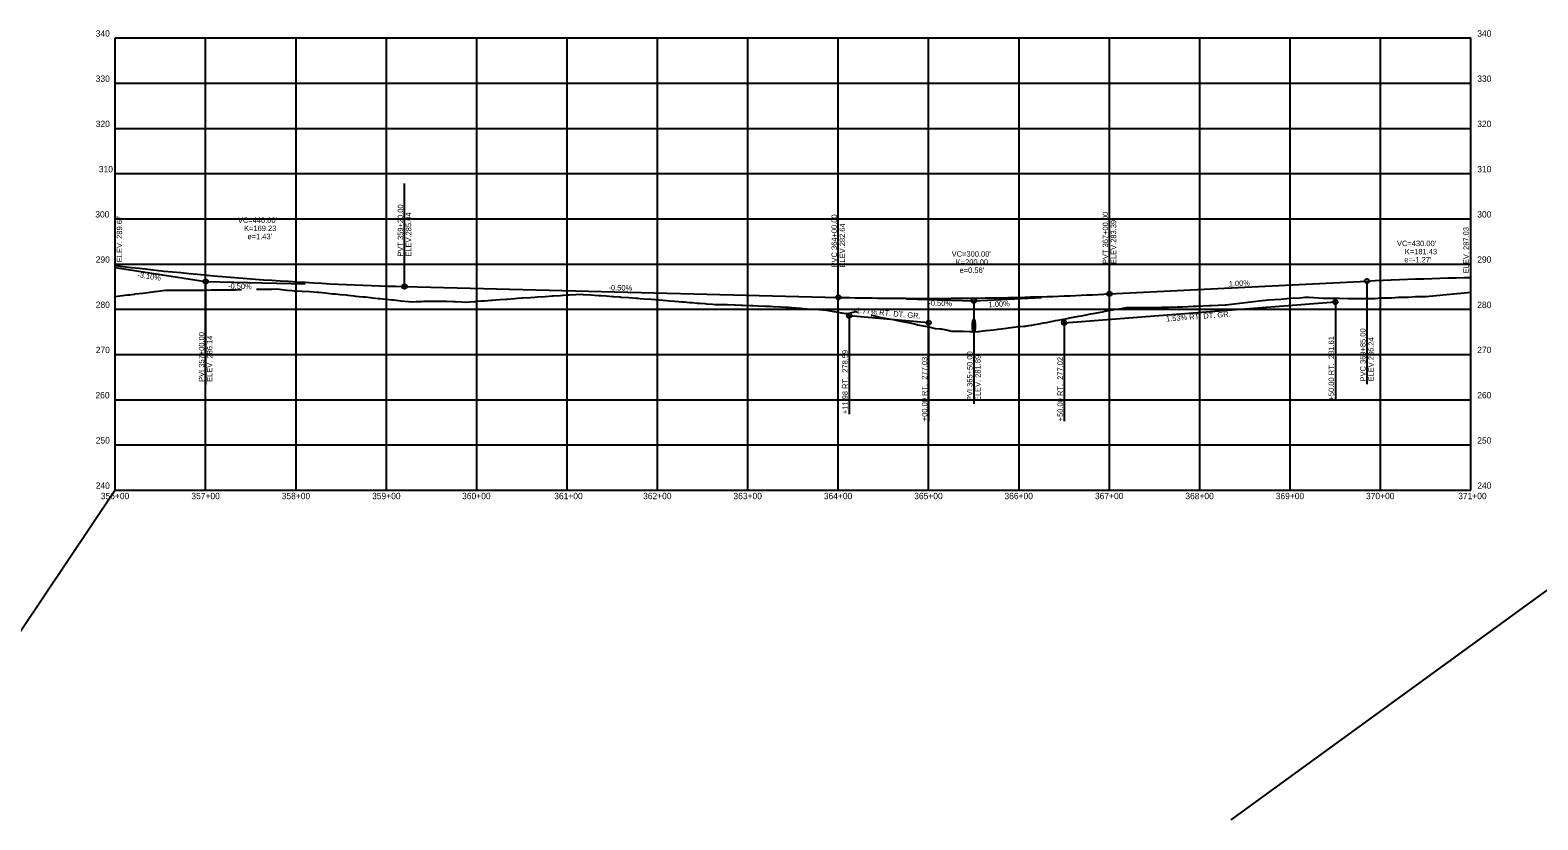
# Model space of a CAD drawing. Extents: x 881054 to 892094, y 1562235 to 1563136.
# Drawn here: x 886308 to 887976, y 1562253 to 1563127 of the extents above; entities that cross this region are included whole.
import ezdxf

# ---------------------------------------------------------------- set-up
doc = ezdxf.new("R2010")
doc.units = 0
for name, color, linetype in [('Default', 7, 'Continuous'), ('R_Axis', 7, 'Continuous'), ('R_Axis Annot', 7, 'Continuous'), ('R_Concrete', 7, 'Continuous'), ('R_Exist Surface', 7, 'Continuous'), ('R_Grid', 7, 'Continuous'), ('R_No Plot', 7, 'Continuous'), ('R_Point Sym', 7, 'Continuous'), ('R_Vert Alg', 7, 'Continuous'), ('R_Vert Alg Annot', 7, 'Continuous')]:
    doc.layers.add(name, color=color, linetype=linetype)

msp = doc.modelspace()

# ---------------------------------------------------------------- linework, layer by layer
at = {"layer": 'Default'}
for p, q in [((887452.2, 1562803), (887752.2, 1562826)), ((887214.2, 1562810.9), (887302.2, 1562803.1))]:
    msp.add_line(p, q, dxfattribs=at)
at = {"layer": 'R_Axis'}
for p, q in [((886402.2, 1562617.9), (886402.2, 1563117.9)), ((887902.2, 1562617.9), (887902.2, 1563117.9)), ((886402.2, 1562617.9), (887902.2, 1562617.9))]:
    msp.add_line(p, q, dxfattribs=at)
at = {"layer": 'R_Concrete'}
msp.add_ellipse((887352.2, 1562799.6), major_axis=(0, 7.5), ratio=0.2, dxfattribs=at)
at = {"layer": 'R_Exist Surface'}
for points in [[(886402.2, 1562832.2), (886407.4, 1562832.7), (886415.8, 1562833.7), (886418.4, 1562834), (886420.7, 1562834.3), (886423.7, 1562834.7), (886424.2, 1562834.8), (886432.6, 1562835.8), (886441, 1562836.8), (886441, 1562836.8), (886445.9, 1562837.5), (886449.4, 1562837.9), (886457.8, 1562838.9), (886458.7, 1562839.1), (886466.2, 1562839.1), (886467.8, 1562839.1), (886474.6, 1562839.1), (886479.3, 1562839.2), (886483, 1562839.1), (886484.9, 1562839.1), (886491.4, 1562839.2), (886498.8, 1562839.2), (886499.8, 1562839.2), (886501.9, 1562839.2), (886508.2, 1562839.3), (886516.6, 1562839.3), (886518.3, 1562839.4), (886518.7, 1562839.4), (886521.4, 1562839.4), (886525, 1562839.4), (886533.4, 1562839.3), (886534.7, 1562839.3), (886541.8, 1562839.7)], [(886558.3, 1562840), (886558.6, 1562840), (886560.1, 1562840), (886567, 1562840.2), (886572, 1562840.2), (886575.5, 1562840.3), (886580.6, 1562840.4), (886583.9, 1562840), (886589.2, 1562839.4), (886592.3, 1562839.1), (886597.5, 1562838.5), (886600.7, 1562838.3), (886609.1, 1562837.8), (886617.5, 1562837.4), (886625.9, 1562836.9), (886627.6, 1562836.8), (886634.3, 1562836.1), (886636.9, 1562835.8), (886642.7, 1562835.1), (886645.9, 1562834.8), (886651.1, 1562834.3), (886657.7, 1562833.7), (886659.5, 1562833.4), (886666.2, 1562832.7), (886667.9, 1562832.5), (886676.3, 1562831.7), (886678.9, 1562831.5), (886684.7, 1562830.8), (886687, 1562830.6), (886693.1, 1562829.9), (886695.1, 1562829.7), (886701.5, 1562829.1), (886708.1, 1562828.4), (886709.9, 1562828.2), (886715.8, 1562827.6), (886718.3, 1562827.4), (886726.7, 1562826.5), (886729.6, 1562826.3), (886735.1, 1562826.4), (886740.8, 1562826.5), (886743.6, 1562826.7), (886745.9, 1562826.9), (886752, 1562826.9), (886760.4, 1562826.9), (886760.5, 1562826.9), (886761.4, 1562827), (886764.5, 1562827), (886768.8, 1562826.7), (886775.9, 1562826.4), (886777.2, 1562826.4), (886778.2, 1562826.4), (886785.6, 1562826.1), (886789.9, 1562825.9), (886794, 1562826.2), (886800.9, 1562826.6), (886802.4, 1562826.8), (886806.6, 1562827.1), (886810.8, 1562827.4), (886818, 1562827.9), (886819.2, 1562828), (886823.3, 1562828.3), (886827.6, 1562828.6), (886835, 1562829.1), (886836, 1562829.2), (886844.4, 1562829.8), (886847.2, 1562830), (886852, 1562830.4), (886852.8, 1562830.5), (886861.2, 1562831), (886866.3, 1562831.4), (886869.4, 1562831.6), (886869.6, 1562831.6), (886878, 1562832.2), (886885.5, 1562832.7), (886886.4, 1562832.8), (886886.7, 1562832.8), (886894.8, 1562833.3), (886897.9, 1562833.5), (886903.2, 1562833.7), (886904.3, 1562833.8), (886911.7, 1562834.1), (886919.6, 1562834.5), (886920.1, 1562834.4), (886928.5, 1562833.8), (886936.9, 1562833.2), (886938.8, 1562833.1), (886940, 1562833), (886945.3, 1562832.6), (886952.3, 1562832.1), (886953.7, 1562832), (886959.8, 1562831.6), (886960.4, 1562831.5), (886961, 1562831.5), (886962.1, 1562831.4), (886970.5, 1562830.8), (886978.9, 1562830.2), (886980.4, 1562830.1), (886982.6, 1562829.9), (886987.3, 1562829.6), (886995.7, 1562829), (886999.9, 1562828.7), (887003.9, 1562828.3), (887004.1, 1562828.3), (887012.5, 1562827.6), (887015.4, 1562827.4), (887020.9, 1562826.9), (887021.2, 1562826.9), (887029.3, 1562826.2), (887031.7, 1562826), (887037.7, 1562825.5), (887040.6, 1562825.3), (887046.1, 1562824.8), (887048.6, 1562824.6), (887054.5, 1562824.1), (887056.5, 1562824), (887062.9, 1562823.5), (887066.1, 1562823.2), (887071.3, 1562823.2), (887076.2, 1562823.1), (887079.8, 1562823), (887087.2, 1562822.7), (887088.2, 1562822.7), (887094.8, 1562822.6), (887096.6, 1562822.5), (887105, 1562822.1), (887107.5, 1562822), (887113.4, 1562821.7), (887121.8, 1562821.3), (887123, 1562821.3), (887127, 1562821.2), (887130.2, 1562821.1), (887138.6, 1562820.6), (887144.2, 1562820.4), (887145.8, 1562820.3), (887147, 1562820.2), (887155.4, 1562819.4), (887155.5, 1562819.4), (887159.8, 1562819.1), (887160.4, 1562819), (887163.8, 1562818.8), (887172.2, 1562818.1), (887174.1, 1562817.9), (887176.5, 1562817.9), (887180.6, 1562817.6), (887189, 1562817), (887189, 1562817), (887197.4, 1562815.3), (887197.6, 1562815.3), (887205.8, 1562813.9), (887211.2, 1562813.1), (887214.2, 1562813.7), (887220, 1562814.9), (887221.9, 1562815.4), (887222.6, 1562815.1), (887223, 1562815)], [(887238.6, 1562811.5), (887239.4, 1562811.3), (887244.2, 1562810.1), (887247.9, 1562809.2), (887249.5, 1562808.8), (887256.3, 1562807.7), (887263, 1562806.5), (887264.7, 1562806.1), (887269.3, 1562805), (887273.1, 1562804.3), (887281.5, 1562802.8), (887281.8, 1562802.8), (887289.2, 1562800.9), (887289.9, 1562800.8), (887298.3, 1562799.3), (887300.7, 1562798.8), (887306.7, 1562797.3), (887309.3, 1562796.7), (887315.1, 1562796.3), (887316.2, 1562796.2), (887323.5, 1562794.7), (887327.6, 1562793.8), (887331.9, 1562793.8), (887336, 1562793.7), (887340.3, 1562793.6), (887347.7, 1562793.5), (887348.7, 1562793.3), (887350.6, 1562793), (887357.1, 1562793.3), (887357.3, 1562793.3), (887362.6, 1562794), (887365.1, 1562794.3), (887365.5, 1562794.3), (887373.9, 1562795.3), (887379, 1562796), (887382.3, 1562796.4), (887388.3, 1562797.1), (887390.7, 1562797.4), (887399.1, 1562798.3), (887403.4, 1562798.7), (887407.5, 1562799.2), (887409.4, 1562799.4), (887413.2, 1562799.9), (887416, 1562800.4), (887416.4, 1562800.4), (887419.6, 1562800.9), (887424.4, 1562801.9), (887429.4, 1562802.9), (887432.5, 1562803.4), (887432.8, 1562803.4), (887441.2, 1562805.1), (887442.4, 1562805.3), (887445.5, 1562805.8), (887449.6, 1562806.6), (887455.5, 1562807.8), (887458.5, 1562808.3), (887468.5, 1562810.2), (887471.4, 1562810.7), (887481.6, 1562812.7), (887484.4, 1562813.2), (887494.6, 1562815.2), (887497.3, 1562815.7), (887507.7, 1562817.7), (887511.2, 1562817.9), (887521.3, 1562819.9), (887525.3, 1562820), (887536.7, 1562819.7), (887542.7, 1562820), (887552.2, 1562819.8), (887560.1, 1562820.2), (887567.8, 1562820.1), (887577.5, 1562820.6), (887583.4, 1562820.6), (887595, 1562821.2), (887599.1, 1562821.2), (887612.5, 1562821.9), (887614.8, 1562822), (887630.1, 1562822.9), (887630.6, 1562822.9), (887631.1, 1562822.9), (887667.8, 1562827.2), (887678.4, 1562828.2), (887692, 1562829.2), (887701.8, 1562830.2), (887713.3, 1562830.7), (887718.8, 1562831.4), (887723, 1562831.4), (887739.1, 1562830.1), (887746.7, 1562830.1), (887756.7, 1562830), (887766.5, 1562829.9), (887774.1, 1562829.9), (887784.1, 1562829.9), (887795.8, 1562829.9), (887802.9, 1562830.5), (887814.5, 1562830.6), (887821.8, 1562831.3), (887833.2, 1562831.3), (887840.9, 1562832.1), (887852.1, 1562832.1), (887860.2, 1562832.9), (887871.6, 1562834), (887883, 1562835), (887891, 1562835.8), (887902.2, 1562836.8)]]:
    msp.add_lwpolyline(points, dxfattribs=at)
at = {"layer": 'R_Grid'}
for p, q in [((886402.2, 1563117.9), (887902.2, 1563117.9)), ((886402.2, 1563117.9), (887902.2, 1563117.9)), ((886502.2, 1562617.9), (886502.2, 1563117.9)), ((886602.2, 1562617.9), (886602.2, 1563117.9)), ((886702.2, 1562617.9), (886702.2, 1563117.9)), ((886802.2, 1562617.9), (886802.2, 1563117.9)), ((886902.2, 1562617.9), (886902.2, 1563117.9)), ((887002.2, 1562617.9), (887002.2, 1563117.9)), ((887102.2, 1562617.9), (887102.2, 1563117.9)), ((887202.2, 1562617.9), (887202.2, 1563117.9)), ((887302.2, 1562617.9), (887302.2, 1563117.9)), ((887402.2, 1562617.9), (887402.2, 1563117.9)), ((887502.2, 1562617.9), (887502.2, 1563117.9)), ((887602.2, 1562617.9), (887602.2, 1563117.9)), ((887702.2, 1562617.9), (887702.2, 1563117.9)), ((887802.2, 1562617.9), (887802.2, 1563117.9)), ((886402.2, 1563067.9), (887902.2, 1563067.9)), ((886402.2, 1563017.9), (887902.2, 1563017.9)), ((886402.2, 1562967.9), (887902.2, 1562967.9)), ((886402.2, 1562917.9), (887902.2, 1562917.9)), ((886402.2, 1562867.9), (887902.2, 1562867.9)), ((886402.2, 1562817.9), (887902.2, 1562817.9)), ((886402.2, 1562767.9), (887902.2, 1562767.9)), ((886402.2, 1562717.9), (887902.2, 1562717.9)), ((886402.2, 1562667.9), (887902.2, 1562667.9))]:
    msp.add_line(p, q, dxfattribs=at)
at = {"layer": 'R_No Plot'}
for p, q in [((886402.2, 1562617.9), (886232.6, 1562365.3)), ((888122.2, 1562606), (887636.7, 1562253.3))]:
    msp.add_line(p, q, dxfattribs=at)
at = {"layer": 'R_Point Sym'}
for points in [[(887752.2, 1562826), (887751.7, 1562826.5), (887752.2, 1562826), (887751.7, 1562825.5), (887752.2, 1562826), (887752.7, 1562825.5), (887752.2, 1562826), (887752.7, 1562826.5)], [(887214.2, 1562810.9), (887213.7, 1562811.4), (887214.2, 1562810.9), (887213.7, 1562810.4), (887214.2, 1562810.9), (887214.7, 1562810.4), (887214.2, 1562810.9), (887214.7, 1562811.4)], [(887302.2, 1562803.1), (887301.7, 1562803.6), (887302.2, 1562803.1), (887301.7, 1562802.6), (887302.2, 1562803.1), (887302.7, 1562802.6), (887302.2, 1562803.1), (887302.7, 1562803.6)], [(887452.2, 1562803), (887451.7, 1562803.5), (887452.2, 1562803), (887451.7, 1562802.5), (887452.2, 1562803), (887452.7, 1562802.5), (887452.2, 1562803), (887452.7, 1562803.5)]]:
    msp.add_lwpolyline(points, dxfattribs=at)
at = {"layer": 'R_Vert Alg'}
for p, q in [((886722.2, 1562843.1), (887202.2, 1562831.1)), ((887502.2, 1562834.9), (887787.2, 1562849.1)), ((887452.2, 1562803), (887752.2, 1562826)), ((887214.2, 1562810.9), (887302.2, 1562803.1))]:
    msp.add_line(p, q, dxfattribs=at)
for points in [[(886402.2, 1562866.3), (886410.6, 1562865.3), (886419.7, 1562864.2), (886428.9, 1562863.2), (886438.1, 1562862.2), (886447.2, 1562861.2), (886456.4, 1562860.2), (886465.6, 1562859.3), (886474.7, 1562858.4), (886483.9, 1562857.5), (886493.1, 1562856.6), (886511.4, 1562855), (886520.6, 1562854.2), (886529.7, 1562853.4), (886538.9, 1562852.7), (886548.1, 1562852), (886557.2, 1562851.3), (886566.4, 1562850.6), (886575.6, 1562850), (886584.7, 1562849.4), (886593.9, 1562848.8), (886603.1, 1562848.2), (886612.2, 1562847.7), (886621.4, 1562847.2), (886630.6, 1562846.7), (886639.7, 1562846.2), (886648.9, 1562845.8), (886658.1, 1562845.3), (886667.2, 1562845), (886676.4, 1562844.6), (886685.6, 1562844.2), (886694.7, 1562843.9), (886703.9, 1562843.6), (886713.1, 1562843.4), (886722.2, 1562843.1)], [(887787.2, 1562849.1), (887796.2, 1562849.6), (887805.2, 1562850), (887814.1, 1562850.4), (887823.1, 1562850.7), (887832, 1562851.1), (887841, 1562851.4), (887850, 1562851.7), (887858.9, 1562852), (887867.9, 1562852.3), (887876.8, 1562852.5), (887885.8, 1562852.7), (887894.7, 1562852.9), (887902.2, 1562853.1)], [(887202.2, 1562831.1), (887208.5, 1562831), (887214.7, 1562830.8), (887221, 1562830.7), (887227.2, 1562830.6), (887233.5, 1562830.5), (887239.7, 1562830.4), (887246, 1562830.3), (887252.2, 1562830.2), (887258.5, 1562830.1), (887264.7, 1562830.1), (887271, 1562830), (887277.2, 1562830), (887283.5, 1562829.9), (887289.7, 1562829.9), (887296, 1562829.9), (887302.2, 1562829.9), (887308.5, 1562829.9), (887314.7, 1562829.9), (887321, 1562829.9), (887327.2, 1562830), (887333.5, 1562830), (887339.7, 1562830.1), (887346, 1562830.1), (887358.5, 1562830.3), (887364.7, 1562830.4), (887371, 1562830.5), (887377.2, 1562830.6), (887383.5, 1562830.7), (887389.7, 1562830.8), (887396, 1562831), (887402.2, 1562831.1), (887408.5, 1562831.3), (887414.7, 1562831.5), (887421, 1562831.6), (887427.2, 1562831.8), (887433.5, 1562832), (887439.7, 1562832.2), (887446, 1562832.5), (887452.2, 1562832.7), (887458.5, 1562832.9), (887464.7, 1562833.2), (887471, 1562833.4), (887477.2, 1562833.7), (887483.5, 1562834), (887489.7, 1562834.3), (887496, 1562834.6), (887502.2, 1562834.9)]]:
    msp.add_lwpolyline(points, dxfattribs=at)
for centre in [(887752.2, 1562826), (887214.2, 1562810.9), (887302.2, 1562803.1), (887452.2, 1562803)]:
    msp.add_circle(centre, 2.5, dxfattribs=at)
at = {"layer": 'R_Vert Alg Annot'}
for p, q in [((886722.2, 1562873.1), (886722.2, 1562957.1)), ((887202.2, 1562861.1), (887202.2, 1562945.1)), ((887502.2, 1562864.9), (887502.2, 1562948.9)), ((886722.2, 1562843.1), (886722.2, 1562873.1)), ((886402.2, 1562864.1), (886502.2, 1562848.6)), ((887202.2, 1562831.1), (887202.2, 1562861.1)), ((887502.2, 1562834.9), (887502.2, 1562864.9)), ((886502.2, 1562848.6), (886612.2, 1562845.9)), ((886502.2, 1562848.6), (886502.2, 1562818.6)), ((887787.2, 1562849.1), (887787.2, 1562819.1)), ((887277.2, 1562829.3), (887352.2, 1562827.4)), ((887352.2, 1562827.4), (887427.2, 1562831.1)), ((887352.2, 1562827.4), (887352.2, 1562797.4)), ((887752.2, 1562826), (887752.2, 1562801)), ((887787.2, 1562819.1), (887787.2, 1562735.1)), ((886502.2, 1562818.6), (886502.2, 1562734.6)), ((887214.2, 1562810.9), (887214.2, 1562785.9)), ((887302.2, 1562803.1), (887302.2, 1562778.1)), ((887452.2, 1562803), (887452.2, 1562778)), ((887214.2, 1562785.9), (887214.2, 1562701.9)), ((887352.2, 1562797.4), (887352.2, 1562713.4)), ((887752.2, 1562801), (887752.2, 1562717)), ((887302.2, 1562778.1), (887302.2, 1562694.1)), ((887452.2, 1562778), (887452.2, 1562694))]:
    msp.add_line(p, q, dxfattribs=at)
for centre in [(886502.2, 1562848.6), (886722.2, 1562843.1), (887502.2, 1562834.9), (887787.2, 1562849.1), (887202.2, 1562831.1), (887352.2, 1562827.4)]:
    msp.add_circle(centre, 2.5, dxfattribs=at)

# ---------------------------------------------------------------- texts
at = {"layer": 'R_Axis Annot'}
for s, height, p in [('340', 7, (886380.6, 1563119.4)), ('340', 7, (886380.6, 1563119.4)), ('340', 7, (887909.2, 1563119.4)), ('340', 7, (887909.2, 1563119.4)), ('330', 7, (886380.6, 1563069.4)), ('330', 7, (887909.2, 1563069.4)), ('320', 7, (886380.6, 1563019.4)), ('320', 7, (887909.2, 1563019.4)), ('310', 7, (886384, 1562969.4)), ('310', 7, (887909.2, 1562969.4)), ('300', 7, (886380.1, 1562919.4)), ('300', 7, (887909.2, 1562919.4)), ('290', 7, (886380.6, 1562869.4)), ('290', 7, (887909.2, 1562869.4)), ('280', 7, (886380.6, 1562819.4)), ('280', 7, (887909.2, 1562819.4)), ('270', 7, (886380.6, 1562769.4)), ('270', 7, (887909.2, 1562769.4)), ('260', 7, (886380.3, 1562719.4)), ('260', 7, (887909.2, 1562719.4)), ('250', 7, (886380.6, 1562669.4)), ('250', 7, (887909.2, 1562669.4)), ('240', 7, (886380.6, 1562619.4)), ('240', 7, (887909.2, 1562619.4)), ('356+00', 7, (886386.2, 1562607.9)), ('-', 0.0001, (886402.2, 1562617.9)), ('357+00', 7, (886486.4, 1562607.9)), ('358+00', 7, (886586.4, 1562607.9)), ('359+00', 7, (886686.4, 1562607.9)), ('360+00', 7, (886786, 1562607.9)), ('361+00', 7, (886887.9, 1562607.9)), ('362+00', 7, (886986.2, 1562607.9)), ('363+00', 7, (887086.2, 1562607.9)), ('364+00', 7, (887186.2, 1562607.9)), ('365+00', 7, (887286.2, 1562607.9)), ('366+00', 7, (887386.1, 1562607.9)), ('367+00', 7, (887486.2, 1562607.9)), ('368+00', 7, (887586.2, 1562607.9)), ('369+00', 7, (887686.2, 1562607.9)), ('370+00', 7, (887786.1, 1562607.9)), ('371+00', 7, (887888.1, 1562607.9))]:
    msp.add_text(s, height=height, dxfattribs=at).set_placement(p)
at = {"layer": 'R_Vert Alg Annot'}
for s, rotation, p in [('ELEV. 289.67', 90, (886409.8, 1562870)), ('PVT 359+20.00', 90, (886720.7, 1562876.1)), ('ELEV.285.04', 90, (886729.7, 1562876.1)), ('PVC 364+00.00', 90, (887200.7, 1562864.1)), ('PVT 367+00.00', 90, (887500.7, 1562867.9)), ('ELEV.282.64', 90, (887209.7, 1562864.1)), ('ELEV.283.39', 90, (887509.7, 1562867.9)), ('ELEV. 287.03', 90, (887899.8, 1562857.7)), ('-3.10%', 351.1893, (886426.3, 1562853.4)), ('-0.50%', 358.5679, (886526.9, 1562840.7)), ('-0.50%', 358.5679, (886947.9, 1562839)), ('1.00%', 2.8624, (887634.4, 1562843)), ('-1.77% RT. DT. GR.', 354.9352, (887218.8, 1562814)), ('-0.50%', 358.5679, (887301.7, 1562821.9)), ('1.00%', 2.8624, (887368.6, 1562820.1)), ('1.53% RT. DT. GR.', 4.3674, (887565, 1562804.3)), ('PVI 357+00.00', 90, (886500.7, 1562737.6)), ('ELEV. 286.14', 90, (886509.7, 1562737.6)), ('+50.00 RT.  281.61', 90, (887750.7, 1562717)), ('PVC 369+85.00', 90, (887785.7, 1562738.1)), ('+11.98 RT.  278.59', 90, (887212.7, 1562701.9)), ('PVI 365+50.00', 90, (887350.7, 1562716.4)), ('ELEV.286.24', 90, (887794.7, 1562738.1)), ('+00.00 RT.  277.03', 90, (887300.7, 1562694.1)), ('ELEV. 281.89', 90, (887359.7, 1562716.4)), ('+50.00 RT.  277.02', 90, (887450.7, 1562694))]:
    msp.add_text(s, height=6, rotation=rotation, dxfattribs=at).set_placement(p)
for s, p in [("VC=440.00'", (886537.9, 1562913.4)), ('K=169.23', (886544.7, 1562904.4)), ("e=1.43'", (886548.5, 1562895.4)), ("VC=430.00'", (887820.4, 1562887.7)), ("VC=300.00'", (887327.7, 1562876.1)), ('K=200.00', (887332.2, 1562867.1)), ("e=-1.27'", (887828.5, 1562869.7)), ('K=181.43', (887829.1, 1562878.7)), ("e=0.56'", (887336.4, 1562858.1))]:
    msp.add_text(s, height=6, dxfattribs=at).set_placement(p)

doc.saveas('drawing.dxf')
